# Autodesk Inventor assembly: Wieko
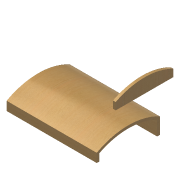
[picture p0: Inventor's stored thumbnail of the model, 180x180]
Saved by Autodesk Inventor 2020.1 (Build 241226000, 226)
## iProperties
Created: 2005-09
Part Number: Wieko
Document SubType Name: Assembly
Designer: F.Stasiak
Manager: www.cadconsulting.pl
Company: Fabian Stasiak CAD Consulting
Author: F.Stasiak
Subject: Zbiór ćwiczeń. Autodesk Inventor 2020. Kurs podstawowy
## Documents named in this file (3)
- C:\2020_Kurs_podstawowy\R6 Zespoły\Wiązania\Skrzynia I\Wieko_0.iam
- C:\2020_Kurs_podstawowy\R6 Zespoły\Wiązania\Skrzynia I\Bok wieka.ipt
- C:\2020_Kurs_podstawowy\R6 Zespoły\Wiązania\Skrzynia I\Wierzch wieka.ipt
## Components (2 placed, 2 different names)
1. Wierzch wieka:1
2. Bok wieka:1
